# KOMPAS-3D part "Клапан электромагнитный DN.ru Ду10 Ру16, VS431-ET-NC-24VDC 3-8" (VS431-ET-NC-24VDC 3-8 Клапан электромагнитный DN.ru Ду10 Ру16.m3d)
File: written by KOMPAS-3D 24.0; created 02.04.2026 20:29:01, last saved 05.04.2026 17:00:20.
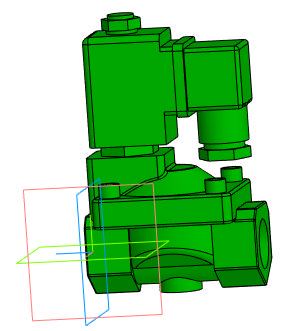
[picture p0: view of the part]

Document properties: Автор: artio; Полное имя файла: ..\VS400-ET-NC-24VDC 3-8 Клапан электромагнитный DN.ru Ду10 Ру16.cdw

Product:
- Body: Тело 1  | qty 1
    Масса: 1.030062
- Part/product: Клапан электромагнитный DN.ru Ду10 Ру16  | designation VS431-ET-NC-24VDC 3-8
    Масса: 0.62
    Раздел спецификации: Прочие изделия
    Форматы листов документа: A3
    Примечание: D130-04739
    additional columns: ef56311e-7521-43dc-8291-0e6108b3d81d; VS400-ET-NC-220VAC 3-8; artio; c; Шероховатость не задана; Да

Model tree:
1. Операция без истории:1

Expressions: VS431-ET-NC-24VDC 3-8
